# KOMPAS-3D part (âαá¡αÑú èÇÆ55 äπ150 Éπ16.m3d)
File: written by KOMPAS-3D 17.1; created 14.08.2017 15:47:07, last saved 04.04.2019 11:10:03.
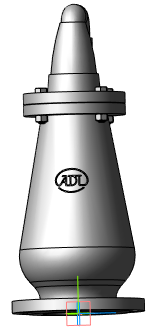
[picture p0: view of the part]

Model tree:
1. Операция без истории:2  (labels: Сталь 20  ГОСТ 1050-2013)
